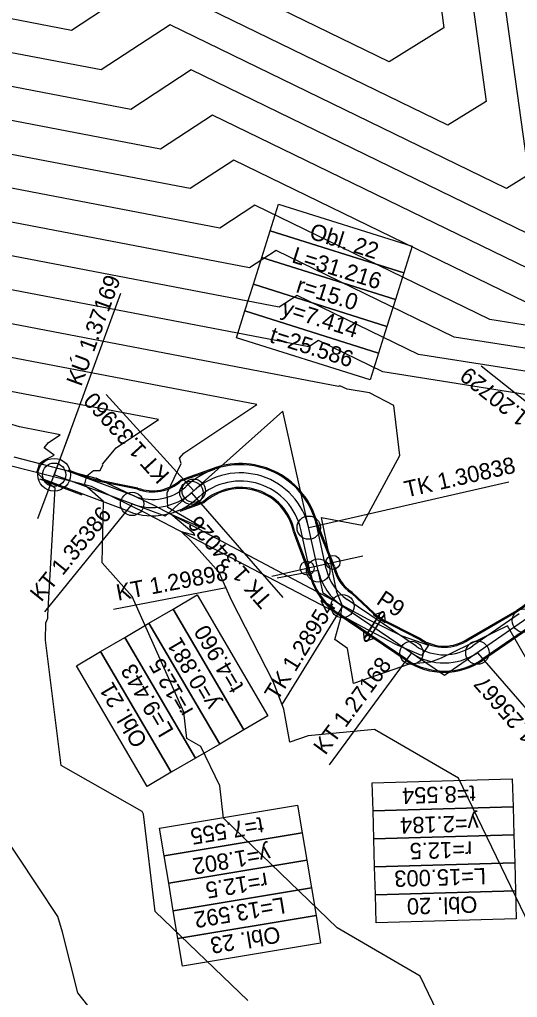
# Model space of a CAD drawing. Extents: x -549394 to -546608, y -1037055 to -1033629.
# Drawn here: x -548577.2 to -548470.6, y -1034132.6 to -1033923 of the extents above; entities that cross this region are included whole.
import ezdxf

# ---------------------------------------------------------------- set-up
doc = ezdxf.new("R2010")
doc.units = 0
for name, color, linetype in [('hlavni_vrst', 7, 'Continuous'), ('hrana_L', 7, 'Continuous'), ('norm_vrst', 7, 'Continuous'), ('POLYGONY_SITUACE_PO', 7, 'Continuous'), ('u_sirka_1_5m', 7, 'Continuous'), ('x_navrh_C21', 7, 'Continuous'), ('x_osa_C21', 7, 'Continuous'), ('x_popis_C21', 7, 'Continuous'), ('x_popis_oblouky_C21', 7, 'Continuous'), ('x_popis_pricne_rezy_C21', 7, 'Continuous'), ('x_popis_velky_C21', 7, 'Continuous'), ('x_propustek', 7, 'Continuous')]:
    doc.layers.add(name, color=color, linetype=linetype)

msp = doc.modelspace()

# ---------------------------------------------------------------- linework, layer by layer
at = {"layer": 'hlavni_vrst'}
for p, q in [((-548490.83, -1033892.03), (-548486.31, -1033924.79)), ((-548498.07, -1033932.01), (-548554.07, -1033904.76)), ((-548486.31, -1033924.79), (-548498.07, -1033932.01)), ((-548540.66, -1033959.22), (-548592.15, -1033949.35)), ((-548531.35, -1033953.11), (-548540.66, -1033959.22)), ((-548468.8, -1033983.55), (-548531.35, -1033953.11)), ((-548508.87, -1034001.61), (-548582.81, -1033987.44)), ((-548508.63, -1034001.45), (-548508.87, -1034001.61)), ((-548507.05, -1034002.22), (-548508.63, -1034001.45)), ((-548502.27, -1034002.98), (-548507.05, -1034002.22)), ((-548497.03, -1034005.7), (-548502.27, -1034002.98)), ((-548495.74, -1034016.38), (-548497.03, -1034005.7)), ((-548503.8, -1034031.37), (-548495.74, -1034016.38)), ((-548512.55, -1034029.73), (-548503.8, -1034031.37)), ((-548509.28, -1034045.68), (-548512.55, -1034029.73)), ((-548508.11, -1034048.48), (-548509.28, -1034045.68)), ((-548508.31, -1034050.2), (-548508.11, -1034048.48)), ((-548508.27, -1034050.67), (-548508.31, -1034050.2)), ((-548509.68, -1034055.82), (-548508.27, -1034050.67)), ((-548472.7, -1034052.91), (-548486.92, -1034059.84)), ((-548457.04, -1034080.4), (-548472.7, -1034052.91)), ((-548506.98, -1034057.77), (-548509.68, -1034055.82)), ((-548505.66, -1034065.25), (-548506.98, -1034057.77)), ((-548489.16, -1034060.7), (-548493.75, -1034061.14)), ((-548486.92, -1034059.84), (-548489.16, -1034060.7)), ((-548493.75, -1034061.14), (-548505.66, -1034065.25))]:
    msp.add_line(p, q, dxfattribs=at)
at = {"layer": 'hrana_L'}
for p, q in [((-548578.47, -1034016.69), (-548560.81, -1034021.29)), ((-548561.83, -1034023.04), (-548579.25, -1034018.6)), ((-548549.74, -1034028.97), (-548561.83, -1034023.04)), ((-548548.37, -1034027.11), (-548560.81, -1034021.29)), ((-548508.87, -1034048.06), (-548548.37, -1034027.11)), ((-548549.74, -1034028.97), (-548509.65, -1034049.9)), ((-548508.87, -1034048.06), (-548502.78, -1034051.42)), ((-548503.81, -1034053.16), (-548509.65, -1034049.9)), ((-548502.78, -1034051.42), (-548495.34, -1034055.08)), ((-548496.63, -1034056.94), (-548503.81, -1034053.16)), ((-548495.34, -1034055.08), (-548489.59, -1034057.06)), ((-548491.15, -1034059.3), (-548496.63, -1034056.94)), ((-548489.59, -1034057.06), (-548491.15, -1034059.3))]:
    msp.add_line(p, q, dxfattribs=at)
at = {"layer": 'norm_vrst'}
for p, q in [((-548482.37, -1033903.58), (-548477.27, -1033940.53)), ((-548549.53, -1033914.43), (-548566.09, -1033925.31)), ((-548485.51, -1033945.59), (-548549.53, -1033914.43)), ((-548473.9, -1033915.12), (-548468.22, -1033956.26)), ((-548566.09, -1033925.31), (-548599.62, -1033918.89)), ((-548544.98, -1033924.1), (-548559.73, -1033933.79)), ((-548472.94, -1033959.16), (-548544.98, -1033924.1)), ((-548559.73, -1033933.79), (-548597.75, -1033926.5)), ((-548553.37, -1033942.27), (-548595.89, -1033934.12)), ((-548540.44, -1033933.77), (-548553.37, -1033942.27)), ((-548460.37, -1033972.73), (-548540.44, -1033933.77)), ((-548477.27, -1033940.53), (-548485.51, -1033945.59)), ((-548547.01, -1033950.75), (-548594.02, -1033941.74)), ((-548535.9, -1033943.44), (-548547.01, -1033950.75)), ((-548461.15, -1033979.82), (-548535.9, -1033943.44)), ((-548534.3, -1033967.7), (-548590.28, -1033956.97)), ((-548468.22, -1033956.26), (-548472.94, -1033959.16)), ((-548526.81, -1033962.78), (-548534.3, -1033967.7)), ((-548476.45, -1033987.28), (-548526.81, -1033962.78)), ((-548527.94, -1033976.18), (-548588.41, -1033964.59)), ((-548521.58, -1033984.65), (-548586.54, -1033972.2)), ((-548522.26, -1033972.45), (-548527.94, -1033976.18)), ((-548484.1, -1033991.02), (-548522.26, -1033972.45)), ((-548515.22, -1033993.13), (-548584.67, -1033979.82)), ((-548517.72, -1033982.11), (-548521.58, -1033984.65)), ((-548491.75, -1033994.75), (-548517.72, -1033982.11)), ((-548448.05, -1033991.78), (-548476.45, -1033987.28)), ((-548445.03, -1033997.2), (-548484.1, -1033991.02)), ((-548513.17, -1033991.78), (-548515.22, -1033993.13)), ((-548499.4, -1033998.49), (-548513.17, -1033991.78)), ((-548526.36, -1034005.51), (-548580.94, -1033995.05)), ((-548442, -1034002.63), (-548491.75, -1033994.75)), ((-548457.93, -1034005.05), (-548499.4, -1033998.49)), ((-548547.43, -1034008.73), (-548579.07, -1034002.67)), ((-548577.2, -1034010.29), (-548591.86, -1034005.88)), ((-548542.04, -1034015.88), (-548526.36, -1034005.51)), ((-548568.49, -1034011.96), (-548577.2, -1034010.29)), ((-548556.52, -1034014.75), (-548547.43, -1034008.73)), ((-548570.99, -1034013.61), (-548568.49, -1034011.96)), ((-548571.97, -1034014.8), (-548570.99, -1034013.61)), ((-548569.82, -1034016.37), (-548571.97, -1034014.8)), ((-548559.44, -1034018.28), (-548556.52, -1034014.75)), ((-548571.95, -1034017.38), (-548569.82, -1034016.37)), ((-548542.95, -1034016.98), (-548542.04, -1034015.88)), ((-548573.51, -1034020.06), (-548573.05, -1034018.76)), ((-548573.05, -1034018.76), (-548572.92, -1034018.14)), ((-548572.92, -1034018.14), (-548571.95, -1034017.38)), ((-548559.97, -1034019.61), (-548559.4, -1034018.42)), ((-548559.4, -1034018.42), (-548559.44, -1034018.28)), ((-548545.58, -1034024.4), (-548542.59, -1034018.14)), ((-548542.59, -1034018.14), (-548542.95, -1034016.98)), ((-548571.51, -1034022.06), (-548573.51, -1034020.06)), ((-548563.21, -1034022.51), (-548562.83, -1034020.76)), ((-548562.83, -1034020.76), (-548561.36, -1034019.63)), ((-548561.36, -1034019.63), (-548559.97, -1034019.61)), ((-548569.59, -1034023.43), (-548571.51, -1034022.06)), ((-548563.26, -1034022.67), (-548563.21, -1034022.51)), ((-548562.74, -1034023.2), (-548563.26, -1034022.67)), ((-548559.23, -1034026.26), (-548562.74, -1034023.2)), ((-548571.15, -1034050.62), (-548569.59, -1034023.43)), ((-548545.48, -1034027.58), (-548545.58, -1034024.4)), ((-548559.5, -1034039.39), (-548559.23, -1034026.26)), ((-548537.43, -1034032.21), (-548545.48, -1034027.58)), ((-548539.86, -1034033.14), (-548544.78, -1034029.01)), ((-548544.78, -1034029.01), (-548537.43, -1034032.21)), ((-548540.57, -1034034.6), (-548542.6, -1034032.7)), ((-548542.6, -1034032.7), (-548539.68, -1034033.46)), ((-548539.68, -1034033.46), (-548539.86, -1034033.14)), ((-548537.43, -1034032.21), (-548537.43, -1034032.21)), ((-548537.43, -1034032.21), (-548537.43, -1034032.21)), ((-548537.43, -1034032.21), (-548537.43, -1034032.21)), ((-548537.43, -1034032.21), (-548537.43, -1034032.21)), ((-548534.44, -1034041.51), (-548540.57, -1034034.6)), ((-548553.09, -1034046.62), (-548559.5, -1034039.39)), ((-548531.83, -1034047.39), (-548534.44, -1034041.51)), ((-548542.06, -1034071.44), (-548553.09, -1034046.62)), ((-548522.9, -1034064.85), (-548531.83, -1034047.39)), ((-548571.63, -1034055.96), (-548571.58, -1034052.28)), ((-548571.58, -1034052.28), (-548571.18, -1034051.26)), ((-548571.18, -1034051.26), (-548571.16, -1034050.99)), ((-548571.16, -1034050.99), (-548571.15, -1034050.62)), ((-548568.28, -1034082.84), (-548571.63, -1034055.96)), ((-548520.59, -1034070.75), (-548522.9, -1034064.85)), ((-548519.35, -1034077.84), (-548520.59, -1034070.75)), ((-548541.35, -1034077.07), (-548542.06, -1034071.44)), ((-548501.19, -1034075.12), (-548515.38, -1034076.47)), ((-548483.22, -1034085.6), (-548501.19, -1034075.12)), ((-548538.35, -1034078.78), (-548541.35, -1034077.07)), ((-548515.38, -1034076.47), (-548519.35, -1034077.84)), ((-548534.35, -1034087.19), (-548538.35, -1034078.78)), ((-548550.96, -1034092.68), (-548568.28, -1034082.84)), ((-548465.87, -1034121.49), (-548483.22, -1034085.6)), ((-548569.05, -1034115.21), (-548586.99, -1034088.17)), ((-548533.51, -1034094.13), (-548534.35, -1034087.19)), ((-548550.66, -1034093.3), (-548550.96, -1034092.68)), ((-548548.15, -1034114.12), (-548550.66, -1034093.3)), ((-548509.17, -1034117.64), (-548533.51, -1034094.13)), ((-548568.02, -1034118.59), (-548569.05, -1034115.21)), ((-548528.34, -1034133.25), (-548548.15, -1034114.12)), ((-548564.7, -1034131.6), (-548568.02, -1034118.59)), ((-548491.42, -1034127.98), (-548509.17, -1034117.64)), ((-548486.29, -1034138.6), (-548491.42, -1034127.98)), ((-548553.4, -1034145.77), (-548564.7, -1034131.6))]:
    msp.add_line(p, q, dxfattribs=at)
at = {"layer": 'POLYGONY_SITUACE_PO'}
for centre in [(-548569.81, -1034020.53), (-548540.4, -1034024.4), (-548539.91, -1034023.96), (-548553.11, -1034026.79), (-548515.27, -1034031.88), (-548513.23, -1034041.06), (-548508.05, -1034048.69), (-548469.21, -1034051.81), (-548493.27, -1034058.72), (-548479.15, -1034058.67)]:
    msp.add_circle(centre, 2.5, dxfattribs=at)
at = {"layer": 'u_sirka_1_5m'}
for centre, radius in [((-548569.81, -1034020.53), 3.5), ((-548510.08, -1034039.32), 1.5), ((-548515.61, -1034040.55), 1.5)]:
    msp.add_circle(centre, radius, dxfattribs=at)
at = {"layer": 'x_navrh_C21'}
for p, q in [((-548561.83, -1034021.39), (-548566.76, -1034019.54)), ((-548542.7, -1034021.61), (-548535.49, -1034019.08)), ((-548542.57, -1034021.83), (-548535.41, -1034019.32)), ((-548563.77, -1034024.93), (-548572.87, -1034021.52)), ((-548551.97, -1034023.62), (-548561.94, -1034021.62)), ((-548551.9, -1034023.38), (-548561.83, -1034021.39)), ((-548537.9, -1034026.35), (-548543.85, -1034028.47)), ((-548537.77, -1034026.57), (-548542.9, -1034028.4)), ((-548509.96, -1034040.29), (-548513.73, -1034030.85)), ((-548509.72, -1034040.22), (-548513.49, -1034030.77)), ((-548515.01, -1034042.17), (-548518.55, -1034032.67)), ((-548514.77, -1034042.09), (-548518.31, -1034032.6)), ((-548506.13, -1034045.93), (-548500.35, -1034051.38)), ((-548505.97, -1034045.74), (-548500.21, -1034051.17)), ((-548494.4, -1034060.38), (-548509.17, -1034050.34)), ((-548481.18, -1034055.68), (-548470.7, -1034049.6)), ((-548481.05, -1034055.89), (-548470.57, -1034049.81)), ((-548491.41, -1034055.92), (-548500.35, -1034051.38)), ((-548491.28, -1034055.71), (-548500.21, -1034051.17)), ((-548468.08, -1034053.46), (-548478.02, -1034060.32))]:
    msp.add_line(p, q, dxfattribs=at)
for centre, radius, start, end in [((-548529.91, -1034035.14), 17, 14.7034, 109.1594), ((-548548.73, -1034015.08), 9.14, 249.2317, 312.3926), ((-548548.73, -1034015.08), 8.89, 249.1003, 312.7193), ((-548529.91, -1034035.14), 11.88, 12.3759, 132.246), ((-548529.91, -1034035.14), 11.63, 12.2898, 132.4914), ((-548501.03, -1034038.35), 9.14, 192.2911, 236.0703), ((-548501.03, -1034038.35), 8.89, 192.1588, 236.2017), ((-548497.6, -1034010.65), 47.33, 304.6289, 319.8797), ((-548497.6, -1034010.65), 47.58, 304.6171, 319.8695), ((-548501.03, -1034038.35), 14.5, 195.0814, 235.8229), ((-548486.25, -1034048.38), 9.14, 235.6277, 304.7139), ((-548486.25, -1034048.38), 8.89, 235.524, 304.7778), ((-548486.25, -1034048.38), 14.5, 235.8229, 304.5937)]:
    msp.add_arc(centre, radius, start, end, dxfattribs=at)
at = {"layer": 'x_osa_C21'}
for points in [[(-548520.82, -1034006.91), (-548546.04, -1034029.43)], [(-548512.15, -1034045.9), (-548520.82, -1034006.91)], [(-548434.5, -1034013.39), (-548463.7, -1034048.01), (-548486.2, -1034063.53)], [(-548546.04, -1034029.43), (-548569.81, -1034020.53)], [(-548486.2, -1034063.53), (-548512.15, -1034045.9)]]:
    msp.add_lwpolyline(points, dxfattribs=at)
for centre, radius, start, end in [((-548529.91, -1034035.14), 15, 12.5402, 131.7781), ((-548548.73, -1034015.08), 12.5, 249.4791, 311.7781), ((-548501.03, -1034038.35), 12.5, 192.5402, 235.8229), ((-548486.25, -1034048.38), 12.5, 235.8229, 304.5937)]:
    msp.add_arc(centre, radius, start, end, dxfattribs=at)
at = {"layer": 'x_popis_oblouky_C21'}
for points in [[(-548521.72, -1033962.55), (-548493.11, -1033971.57), (-548494.91, -1033977.29), (-548523.52, -1033968.27)], [(-548523.52, -1033968.27), (-548494.91, -1033977.29), (-548496.71, -1033983.01), (-548525.32, -1033974)], [(-548525.32, -1033974), (-548496.71, -1033983.01), (-548498.51, -1033988.73), (-548527.13, -1033979.72)], [(-548527.13, -1033979.72), (-548498.51, -1033988.73), (-548500.32, -1033994.46), (-548528.93, -1033985.44)], [(-548528.93, -1033985.44), (-548500.32, -1033994.46), (-548502.12, -1034000.18), (-548530.73, -1033991.17)], [(-548529.17, -1034075.21), (-548544.34, -1034049.33), (-548539.16, -1034046.3), (-548524, -1034072.18)], [(-548534.35, -1034078.25), (-548549.52, -1034052.36), (-548544.34, -1034049.33), (-548529.17, -1034075.21)], [(-548539.53, -1034081.28), (-548554.69, -1034055.4), (-548549.52, -1034052.36), (-548534.35, -1034078.25)], [(-548544.71, -1034084.31), (-548559.87, -1034058.43), (-548554.69, -1034055.4), (-548539.53, -1034081.28)], [(-548549.88, -1034087.35), (-548565.05, -1034061.46), (-548559.87, -1034058.43), (-548544.71, -1034084.31)], [(-548471.51, -1034091.71), (-548501.49, -1034092.57), (-548501.67, -1034086.57), (-548471.68, -1034085.71)], [(-548516.67, -1034097.25), (-548546.26, -1034102.18), (-548547.25, -1034096.26), (-548517.65, -1034091.33)], [(-548471.33, -1034097.7), (-548501.32, -1034098.56), (-548501.49, -1034092.57), (-548471.51, -1034091.71)], [(-548515.68, -1034103.17), (-548545.27, -1034108.1), (-548546.26, -1034102.18), (-548516.67, -1034097.25)], [(-548471.16, -1034103.7), (-548501.15, -1034104.56), (-548501.32, -1034098.56), (-548471.33, -1034097.7)], [(-548514.69, -1034109.08), (-548544.29, -1034114.02), (-548545.27, -1034108.1), (-548515.68, -1034103.17)], [(-548470.99, -1034109.7), (-548500.98, -1034110.56), (-548501.15, -1034104.56), (-548471.16, -1034103.7)], [(-548513.71, -1034115), (-548543.3, -1034119.93), (-548544.29, -1034114.02), (-548514.69, -1034109.08)], [(-548470.82, -1034115.7), (-548500.8, -1034116.56), (-548500.98, -1034110.56), (-548470.99, -1034109.7)], [(-548512.72, -1034120.92), (-548542.31, -1034125.85), (-548543.3, -1034119.93), (-548513.71, -1034115)]]:
    msp.add_lwpolyline(points, close=True, dxfattribs=at)
for points in [[(-548555.57, -1033981.69), (-548569.81, -1034020.53)], [(-548478.34, -1033997.22), (-548443.91, -1034024.56)], [(-548558.69, -1034003.31), (-548539.91, -1034023.96)], [(-548472.41, -1034022.13), (-548515.27, -1034031.88)], [(-548540.4, -1034024.4), (-548520.79, -1034046.83)], [(-548553.11, -1034026.79), (-548571.87, -1034049.94)], [(-548513.23, -1034041.06), (-548522, -1034042.73)], [(-548532.93, -1034044.8), (-548557.07, -1034049.39)], [(-548508.05, -1034048.69), (-548521.06, -1034069.76)], [(-548493.27, -1034058.72), (-548510.92, -1034082.73)], [(-548479.15, -1034058.67), (-548459.61, -1034081.16)]]:
    msp.add_lwpolyline(points, dxfattribs=at)
at = {"layer": 'x_popis_pricne_rezy_C21'}
for points in [[(-548573.32, -1034029.9), (-548569.81, -1034020.53), (-548566.31, -1034011.17)], [(-548523.21, -1034042.24), (-548513.45, -1034040.07), (-548503.69, -1034037.89)]]:
    msp.add_lwpolyline(points, dxfattribs=at)
at = {"layer": 'x_popis_velky_C21'}
for p, q in [((-548552.5, -1034025.15), (-548567.24, -1034019.63)), ((-548553.73, -1034028.42), (-548572.39, -1034021.44)), ((-548541.07, -1034022.65), (-548541.57, -1034023.09)), ((-548538.74, -1034025.26), (-548539.24, -1034025.7)), ((-548511.52, -1034040.68), (-548513.56, -1034031.5)), ((-548514.94, -1034041.44), (-548516.98, -1034032.26)), ((-548492.29, -1034057.27), (-548507.06, -1034047.24)), ((-548494.26, -1034060.17), (-548509.03, -1034050.14)), ((-548470.2, -1034050.37), (-548480.15, -1034057.23)), ((-548468.22, -1034053.25), (-548478.16, -1034060.11))]:
    msp.add_line(p, q, dxfattribs=at)
for centre, radius, start, end in [((-548529.91, -1034035.14), 16.75, 12.5402, 131.7781), ((-548548.73, -1034015.08), 10.75, 249.4791, 311.7781), ((-548529.91, -1034035.14), 13.25, 12.5402, 131.7781), ((-548548.73, -1034015.08), 14.25, 249.4791, 311.7781), ((-548501.03, -1034038.35), 14.25, 192.5402, 235.8229), ((-548501.03, -1034038.35), 10.75, 192.5402, 235.8229), ((-548486.25, -1034048.38), 10.75, 235.8229, 304.5937), ((-548486.25, -1034048.38), 14.25, 235.8229, 304.5937)]:
    msp.add_arc(centre, radius, start, end, dxfattribs=at)
at = {"layer": 'x_propustek'}
for p, q in [((-548503.2, -1034055.29), (-548500.06, -1034050.33)), ((-548503.13, -1034055.33), (-548499.99, -1034050.37)), ((-548501.42, -1034050.59), (-548499.46, -1034049.91)), ((-548499.1, -1034050.14), (-548499.46, -1034049.91)), ((-548499.1, -1034050.14), (-548498.89, -1034052.2)), ((-548502.43, -1034055.77), (-548499.3, -1034050.82)), ((-548502.37, -1034055.81), (-548499.23, -1034050.86)), ((-548501.42, -1034050.59), (-548498.89, -1034052.2)), ((-548501.11, -1034050.79), (-548501, -1034050.62)), ((-548501.02, -1034050.85), (-548500.81, -1034050.51)), ((-548500.94, -1034050.9), (-548500.83, -1034050.73)), ((-548499.37, -1034051.89), (-548499.26, -1034051.72)), ((-548499.28, -1034051.95), (-548499.07, -1034051.61)), ((-548499.2, -1034052), (-548499.09, -1034051.83)), ((-548503.33, -1034056.01), (-548503.54, -1034053.94)), ((-548501.01, -1034055.55), (-548503.54, -1034053.94)), ((-548503.15, -1034054.2), (-548503.36, -1034054.53)), ((-548503.23, -1034054.14), (-548503.34, -1034054.31)), ((-548503.06, -1034054.25), (-548503.17, -1034054.42)), ((-548503.33, -1034056.01), (-548502.97, -1034056.23)), ((-548501.01, -1034055.55), (-548502.97, -1034056.23)), ((-548501.41, -1034055.3), (-548501.62, -1034055.63)), ((-548501.49, -1034055.24), (-548501.6, -1034055.41)), ((-548501.32, -1034055.35), (-548501.43, -1034055.52))]:
    msp.add_line(p, q, dxfattribs=at)
for points in [[(-548499.24, -1034049.96), (-548499.26, -1034049.95), (-548499.27, -1034049.94), (-548499.3, -1034049.93), (-548499.31, -1034049.93), (-548499.36, -1034049.91), (-548499.39, -1034049.91), (-548499.5, -1034049.91), (-548499.57, -1034049.92), (-548499.73, -1034049.99), (-548499.8, -1034050.04), (-548499.94, -1034050.17), (-548500, -1034050.25), (-548500.11, -1034050.42), (-548500.15, -1034050.51), (-548500.21, -1034050.69), (-548500.22, -1034050.78), (-548500.22, -1034050.95), (-548500.2, -1034051.02), (-548500.17, -1034051.1), (-548500.16, -1034051.12), (-548500.14, -1034051.14), (-548500.13, -1034051.16), (-548500.1, -1034051.19), (-548500.07, -1034051.21), (-548500.05, -1034051.23)], [(-548499.28, -1034050.02), (-548499.3, -1034050.01), (-548499.33, -1034050), (-548499.37, -1034049.99), (-548499.4, -1034049.98), (-548499.46, -1034049.98), (-548499.49, -1034049.99), (-548499.55, -1034050), (-548499.58, -1034050.01), (-548499.65, -1034050.04), (-548499.69, -1034050.06), (-548499.75, -1034050.11), (-548499.79, -1034050.13), (-548499.88, -1034050.22), (-548499.94, -1034050.29), (-548500.05, -1034050.45), (-548500.08, -1034050.54), (-548500.12, -1034050.66), (-548500.13, -1034050.7), (-548500.14, -1034050.79), (-548500.15, -1034050.82), (-548500.15, -1034050.9), (-548500.14, -1034050.93), (-548500.13, -1034051), (-548500.12, -1034051.03), (-548500.09, -1034051.08), (-548500.08, -1034051.1), (-548500.05, -1034051.14), (-548500.03, -1034051.15), (-548499.99, -1034051.18), (-548499.97, -1034051.19), (-548499.92, -1034051.2), (-548499.89, -1034051.21), (-548499.84, -1034051.21), (-548499.8, -1034051.2), (-548499.74, -1034051.19), (-548499.71, -1034051.18), (-548499.64, -1034051.15), (-548499.61, -1034051.13), (-548499.54, -1034051.08), (-548499.5, -1034051.06), (-548499.41, -1034050.97), (-548499.35, -1034050.9), (-548499.25, -1034050.74), (-548499.21, -1034050.65), (-548499.17, -1034050.53), (-548499.16, -1034050.48), (-548499.15, -1034050.4), (-548499.14, -1034050.36), (-548499.15, -1034050.29), (-548499.15, -1034050.25), (-548499.16, -1034050.19), (-548499.17, -1034050.16), (-548499.2, -1034050.11), (-548499.21, -1034050.09), (-548499.25, -1034050.05), (-548499.26, -1034050.04), (-548499.28, -1034050.02)], [(-548500.05, -1034051.23), (-548500.03, -1034051.24), (-548500.02, -1034051.25), (-548499.99, -1034051.26), (-548499.98, -1034051.26), (-548499.93, -1034051.28), (-548499.9, -1034051.28), (-548499.79, -1034051.28), (-548499.72, -1034051.26), (-548499.57, -1034051.2), (-548499.49, -1034051.14), (-548499.35, -1034051.02), (-548499.29, -1034050.94), (-548499.18, -1034050.77), (-548499.14, -1034050.68), (-548499.08, -1034050.5), (-548499.07, -1034050.41), (-548499.07, -1034050.24), (-548499.09, -1034050.17), (-548499.13, -1034050.09), (-548499.13, -1034050.07), (-548499.15, -1034050.05), (-548499.16, -1034050.03), (-548499.19, -1034050), (-548499.22, -1034049.98), (-548499.24, -1034049.96)], [(-548502.38, -1034054.91), (-548502.4, -1034054.9), (-548502.41, -1034054.9), (-548502.44, -1034054.88), (-548502.45, -1034054.88), (-548502.5, -1034054.87), (-548502.53, -1034054.86), (-548502.63, -1034054.86), (-548502.71, -1034054.88), (-548502.86, -1034054.95), (-548502.94, -1034055), (-548503.08, -1034055.13), (-548503.14, -1034055.2), (-548503.25, -1034055.37), (-548503.29, -1034055.46), (-548503.35, -1034055.64), (-548503.36, -1034055.73), (-548503.36, -1034055.9), (-548503.34, -1034055.98), (-548503.3, -1034056.05), (-548503.3, -1034056.07), (-548503.28, -1034056.1), (-548503.27, -1034056.11), (-548503.24, -1034056.15), (-548503.21, -1034056.17), (-548503.19, -1034056.18)], [(-548503.15, -1034056.12), (-548503.13, -1034056.13), (-548503.1, -1034056.14), (-548503.06, -1034056.16), (-548503.03, -1034056.16), (-548502.97, -1034056.16), (-548502.94, -1034056.16), (-548502.88, -1034056.14), (-548502.85, -1034056.13), (-548502.78, -1034056.1), (-548502.74, -1034056.08), (-548502.68, -1034056.03), (-548502.64, -1034056.01), (-548502.55, -1034055.92), (-548502.49, -1034055.85), (-548502.38, -1034055.69), (-548502.35, -1034055.6), (-548502.31, -1034055.48), (-548502.3, -1034055.44), (-548502.29, -1034055.36), (-548502.28, -1034055.32), (-548502.28, -1034055.24), (-548502.29, -1034055.21), (-548502.3, -1034055.14), (-548502.31, -1034055.12), (-548502.34, -1034055.06), (-548502.35, -1034055.04), (-548502.38, -1034055), (-548502.4, -1034054.99), (-548502.44, -1034054.96), (-548502.46, -1034054.95), (-548502.51, -1034054.94), (-548502.54, -1034054.94), (-548502.59, -1034054.94), (-548502.62, -1034054.94), (-548502.69, -1034054.95), (-548502.72, -1034054.97), (-548502.79, -1034055), (-548502.82, -1034055.02), (-548502.89, -1034055.06), (-548502.93, -1034055.09), (-548503.02, -1034055.18), (-548503.08, -1034055.25), (-548503.18, -1034055.41), (-548503.22, -1034055.49), (-548503.26, -1034055.62), (-548503.27, -1034055.66), (-548503.28, -1034055.74), (-548503.29, -1034055.78), (-548503.28, -1034055.85), (-548503.28, -1034055.89), (-548503.27, -1034055.95), (-548503.26, -1034055.98), (-548503.23, -1034056.03), (-548503.22, -1034056.05), (-548503.18, -1034056.09), (-548503.17, -1034056.11), (-548503.15, -1034056.12)], [(-548503.19, -1034056.18), (-548503.17, -1034056.19), (-548503.16, -1034056.2), (-548503.13, -1034056.21), (-548503.12, -1034056.22), (-548503.07, -1034056.23), (-548503.04, -1034056.23), (-548502.93, -1034056.23), (-548502.86, -1034056.22), (-548502.7, -1034056.15), (-548502.63, -1034056.1), (-548502.49, -1034055.97), (-548502.43, -1034055.89), (-548502.32, -1034055.72), (-548502.28, -1034055.63), (-548502.22, -1034055.45), (-548502.21, -1034055.36), (-548502.21, -1034055.19), (-548502.23, -1034055.12), (-548502.26, -1034055.04), (-548502.27, -1034055.03), (-548502.29, -1034055), (-548502.3, -1034054.99), (-548502.33, -1034054.95), (-548502.36, -1034054.93), (-548502.38, -1034054.91)]]:
    msp.add_open_spline(points, degree=3, dxfattribs=at)

# ---------------------------------------------------------------- texts
at = {"layer": 'x_popis_C21'}
msp.add_text('P9', height=3.5, rotation=326.2792, dxfattribs=at).set_placement((-548501.01, -1034048.05))
at = {"layer": 'x_popis_oblouky_C21'}
for s, rotation, p in [('Obl. 22', 342.5369, (-548515.37, -1033969.85)), ('L=31.216', 342.5369, (-548519.12, -1033974.96)), ('KÚ 1.37169', 69.8543, (-548564.01, -1034001.77)), ('r=15.0', 342.5369, (-548518.2, -1033981.36)), ('y=7.414', 342.5369, (-548521.32, -1033986.21)), ('t=25.586', 342.5369, (-548523.9, -1033992.06)), ('KT 1.20729', 141.5499, (-548462.07, -1034012.26)), ('KT 1.33960', 132.2955, (-548544.89, -1034020.43)), ('TK 1.30838', 12.8287, (-548494.35, -1034025.42)), ('KT 1.35386', 50.9927, (-548572.56, -1034047.96)), ('TK 1.34026', 131.153, (-548522.84, -1034047.21)), ('KT 1.29898', 10.7568, (-548556.14, -1034047.56)), ('TK 1.28954', 58.3045, (-548521.98, -1034069.16)), ('t=4.960', 120.3895, (-548529.06, -1034065.93)), ('y=0.881', 120.3895, (-548534.3, -1034069.54)), ('r=12.5', 120.3895, (-548539.87, -1034071.04)), ('KT 1.27168', 53.6756, (-548511.71, -1034080.79)), ('L=9.443', 120.3895, (-548544.07, -1034075.4)), ('Obl. 21', 120.3895, (-548549.69, -1034077.68)), ('TK 1.25667', 130.9964, (-548461.65, -1034081.53)), ('t=8.554', 181.6679, (-548479.59, -1034087.14)), ('t=7.555', 189.4842, (-548525.3, -1034093.83)), ('y=2.184', 181.6679, (-548478.95, -1034093.48)), ('y=1.802', 189.4842, (-548523.8, -1034100.02)), ('r=12.5', 181.6679, (-548480.3, -1034099.08)), ('L=15.003', 181.6679, (-548477.34, -1034104.82)), ('r=12.5', 189.4842, (-548524.38, -1034105.75)), ('L=13.592', 189.4842, (-548520.66, -1034111.04)), ('Obl. 20', 181.6679, (-548479.21, -1034110.88)), ('Obl. 23', 189.4842, (-548521.69, -1034117.29))]:
    msp.add_text(s, height=3.5, rotation=rotation, dxfattribs=at).set_placement(p)

doc.saveas('drawing.dxf')
